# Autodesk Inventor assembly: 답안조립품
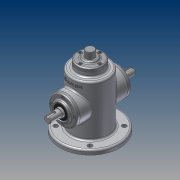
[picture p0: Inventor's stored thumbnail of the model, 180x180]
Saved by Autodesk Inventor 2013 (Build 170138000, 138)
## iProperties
Created: 2014-12
Part Number: 답안조립품
Document SubType Name: Assembly
Designer: CAD-B13
Author: CAD-B13
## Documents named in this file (12)
- C:\Users\CAD-B13\Desktop\441228V1013\답안조립품.iam
- C:\Users\CAD-B13\Desktop\441228V1013\본체.ipt
- C:\Users\CAD-B13\Desktop\441228V1013\베어링 6002.ipt
- 베어링 6002.ipt
- C:\Users\CAD-B13\Desktop\441228V1013\슬라이드.ipt
- C:\Users\CAD-B13\Desktop\441228V1013\편심축2.ipt
- C:\Users\CAD-B13\Desktop\441228V1013\M3x0.5x8.ipt
- M3x0.5.ipt
- C:\Users\CAD-B13\Desktop\441228V1013\오일실.ipt
- 오일실.ipt
- C:\Users\CAD-B13\Desktop\441228V1013\커버.ipt
- C:\Users\CAD-B13\Desktop\441228V1013\상단커버.ipt
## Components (12 placed, 1 different names)
1. M3x0.5:1 — 각도:1
2. M3x0.5:3
3. M3x0.5:4
4. M3x0.5:5
5. M3x0.5:2 — 각도:2
6. M3x0.5:6
7. M3x0.5:7
8. M3x0.5:8
9. M3x0.5:9 — 각도:3
10. M3x0.5:10
11. M3x0.5:11
12. M3x0.5:12
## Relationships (3: Angle 3)
- 각도:1 [Angle]: M3x0.5:1
- 각도:2 [Angle]: M3x0.5:2
- 각도:3 [Angle]: M3x0.5:9
